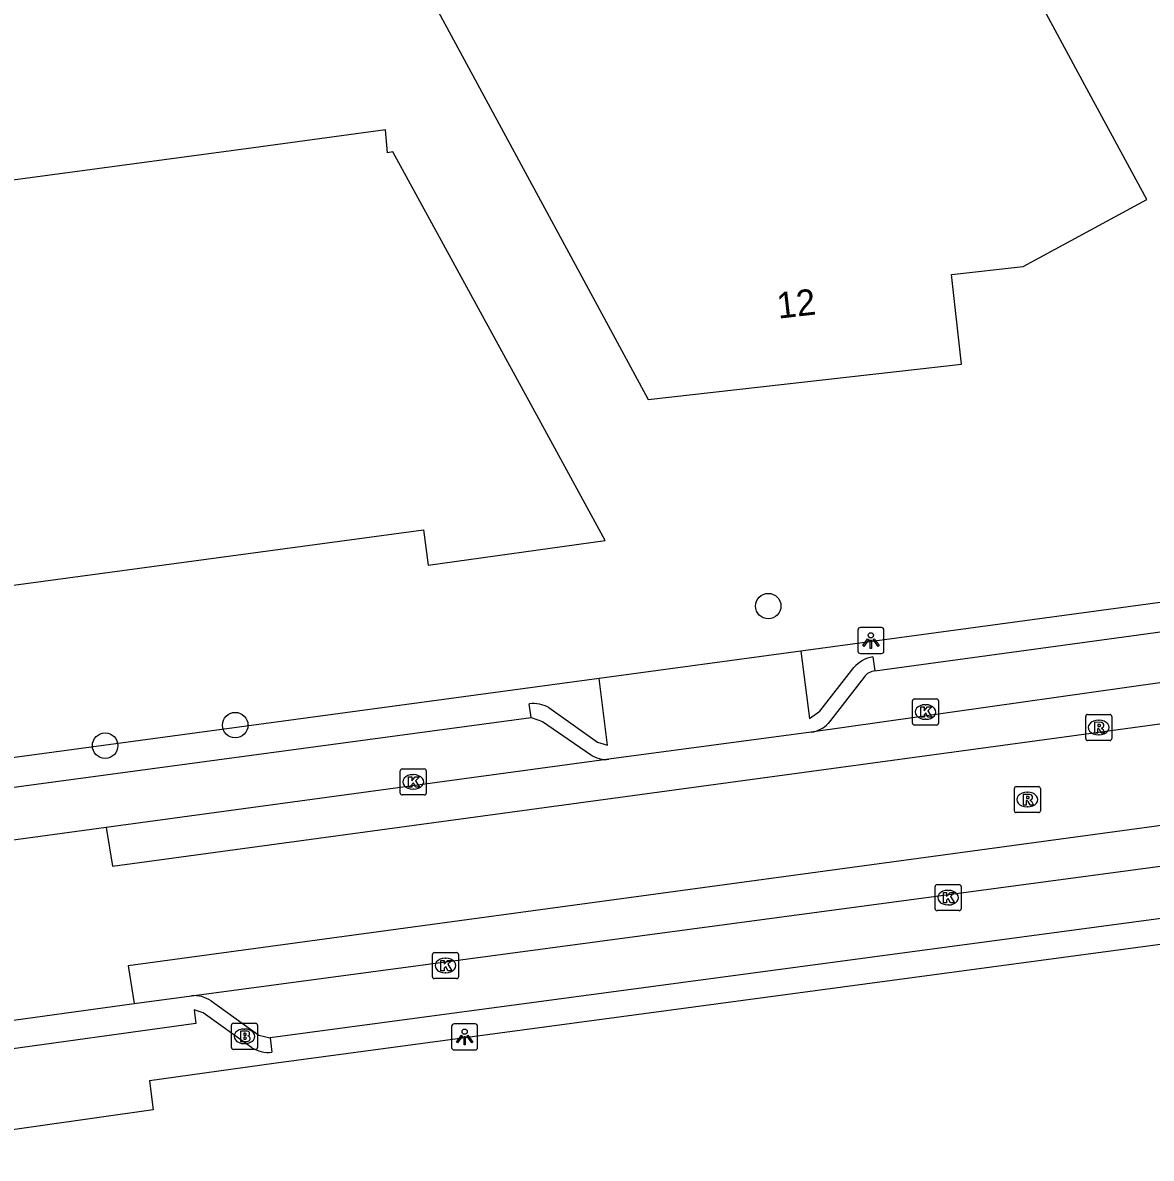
# Model space of a CAD drawing. Extents: x 158461 to 159795, y 387220 to 388672.
# Drawn here: x 158908.52 to 158951.86, y 387443.73 to 387487.32 of the extents above; entities that cross this region are included whole.
import ezdxf

# ---------------------------------------------------------------- set-up
doc = ezdxf.new("R2010")
doc.units = 0
for name, color, linetype in [('IMGEO_Boom', 7, 'Continuous'), ('IMGEO_Brandkraan', 7, 'Continuous'), ('IMGEO_Kolk', 7, 'Continuous'), ('IMGEO_Lichtpunt', 7, 'Continuous'), ('IMGEO_Pand', 7, 'Continuous'), ('IMGEO_Pand_nummerreeks', 7, 'Continuous'), ('IMGEO_Rijbaan_lokaal_gesloten', 7, 'Continuous'), ('IMGEO_Rioolput', 7, 'Continuous'), ('IMGEO_Voetpad_open', 7, 'Continuous')]:
    doc.layers.add(name, color=color, linetype=linetype)

msp = doc.modelspace()

# ---------------------------------------------------------------- linework, layer by layer
at = {"layer": 'IMGEO_Boom'}
for centre in [(158937.148, 387464.927), (158916.678, 387460.357), (158911.683, 387459.569)]:
    msp.add_circle(centre, 0.489, dxfattribs=at)
at = {"layer": 'IMGEO_Brandkraan'}
for p, q in [((158916.534, 387447.985), (158916.534, 387448.837)), ((158916.609, 387448.911), (158917.461, 387448.911)), ((158917.022, 387448.691), (158917.047, 387448.691)), ((158917.535, 387448.837), (158917.535, 387447.985)), ((158917.461, 387447.911), (158916.609, 387447.911)), ((158917.045, 387448.131), (158917.02, 387448.131))]:
    msp.add_line(p, q, dxfattribs=at)
for points in [[(158916.534, 387447.985), (158916.534, 387448.837)], [(158916.609, 387448.911), (158917.461, 387448.911)], [(158917.535, 387448.837), (158917.535, 387447.985)], [(158916.882, 387448.611), (158916.882, 387448.211), (158917.095, 387448.211)], [(158917.113, 387448.611), (158916.882, 387448.611)], [(158917.061, 387448.53), (158917.007, 387448.53), (158917.007, 387448.454)], [(158917.007, 387448.454), (158917.06, 387448.454)], [(158917.069, 387448.378), (158917.007, 387448.378), (158917.007, 387448.297)], [(158917.007, 387448.297), (158917.069, 387448.297)], [(158917.461, 387447.911), (158916.609, 387447.911)]]:
    msp.add_lwpolyline(points, dxfattribs=at)
for centre, radius, start, end in [((158916.611, 387448.835), 0.0765, 91.552, 178.448), ((158916.611, 387448.835), 0.0765, 91.552, 178.448), ((158917.459, 387448.835), 0.0765, 1.552, 88.448), ((158917.459, 387448.835), 0.0765, 1.552, 88.448), ((158917.062, 387448.492), 0.0379, 267.8285, 90.9355), ((158917.07, 387448.337), 0.0404, 269.8759, 90.5077), ((158917.101, 387448.462), 0.251, 268.6676, 293.5347), ((158917.117, 387448.466), 0.145, 59.4692, 91.5367), ((158917.142, 387448.513), 0.0922, 285.5137, 58.1501), ((158917.147, 387448.321), 0.105, 301.3115, 78.989), ((158916.611, 387447.987), 0.0765, 181.552, 268.448), ((158916.611, 387447.987), 0.0765, 181.552, 268.448), ((158917.459, 387447.987), 0.0765, 271.552, 358.448), ((158917.459, 387447.987), 0.0765, 271.552, 358.448)]:
    msp.add_arc(centre, radius, start, end, dxfattribs=at)
for centre, major_axis, ratio, start_param, end_param in [((158917.021, 387448.411), (-0.387, 0.002), 0.722429, 4.712389, 7.853982), ((158917.046, 387448.411), (-0.39, 0.002), 0.717154, 1.570796, 4.712389)]:
    msp.add_ellipse(centre, major_axis=major_axis, ratio=ratio, start_param=start_param, end_param=end_param, dxfattribs=at)
at = {"layer": 'IMGEO_Kolk'}
for p, q in [((158942.687, 387460.435), (158942.687, 387461.287)), ((158942.762, 387461.361), (158943.614, 387461.361)), ((158943.688, 387461.287), (158943.688, 387460.435)), ((158943.175, 387461.141), (158943.2, 387461.141)), ((158943.198, 387460.581), (158943.173, 387460.581)), ((158943.614, 387460.361), (158942.762, 387460.361)), ((158923.089, 387458.676), (158923.941, 387458.676)), ((158923.014, 387457.75), (158923.014, 387458.602)), ((158923.502, 387458.456), (158923.527, 387458.456)), ((158924.015, 387458.602), (158924.015, 387457.75)), ((158923.525, 387457.896), (158923.5, 387457.896)), ((158923.941, 387457.676), (158923.089, 387457.676)), ((158943.556, 387453.309), (158943.556, 387454.161)), ((158943.631, 387454.235), (158944.483, 387454.235)), ((158944.044, 387454.015), (158944.069, 387454.015)), ((158944.557, 387454.161), (158944.557, 387453.309)), ((158944.067, 387453.455), (158944.042, 387453.455)), ((158944.483, 387453.235), (158943.631, 387453.235)), ((158924.253, 387450.701), (158924.253, 387451.553)), ((158924.328, 387451.627), (158925.18, 387451.627)), ((158924.741, 387451.407), (158924.766, 387451.407)), ((158925.254, 387451.553), (158925.254, 387450.701)), ((158924.764, 387450.847), (158924.739, 387450.847)), ((158925.18, 387450.627), (158924.328, 387450.627))]:
    msp.add_line(p, q, dxfattribs=at)
for points in [[(158942.687, 387460.435), (158942.687, 387461.287)], [(158942.762, 387461.361), (158943.614, 387461.361)], [(158943.688, 387461.287), (158943.688, 387460.435)], [(158943.008, 387461.061), (158943.131, 387461.061), (158943.131, 387460.91), (158943.261, 387461.061), (158943.425, 387461.061), (158943.279, 387460.91), (158943.432, 387460.661), (158943.28, 387460.661), (158943.195, 387460.825), (158943.131, 387460.758), (158943.131, 387460.661), (158943.008, 387460.661), (158943.008, 387461.061)], [(158943.614, 387460.361), (158942.762, 387460.361)], [(158923.089, 387458.676), (158923.941, 387458.676)], [(158923.014, 387457.75), (158923.014, 387458.602)], [(158923.335, 387458.376), (158923.458, 387458.376), (158923.458, 387458.225), (158923.588, 387458.376), (158923.752, 387458.376), (158923.606, 387458.225), (158923.759, 387457.976), (158923.607, 387457.976), (158923.522, 387458.14), (158923.458, 387458.073), (158923.458, 387457.976), (158923.335, 387457.976), (158923.335, 387458.376)], [(158924.015, 387458.602), (158924.015, 387457.75)], [(158923.941, 387457.676), (158923.089, 387457.676)], [(158943.556, 387453.309), (158943.556, 387454.161)], [(158943.631, 387454.235), (158944.483, 387454.235)], [(158943.877, 387453.935), (158944, 387453.935), (158944, 387453.784), (158944.13, 387453.935), (158944.294, 387453.935), (158944.148, 387453.784), (158944.301, 387453.535), (158944.149, 387453.535), (158944.064, 387453.699), (158944, 387453.632), (158944, 387453.535), (158943.877, 387453.535), (158943.877, 387453.935)], [(158944.557, 387454.161), (158944.557, 387453.309)], [(158944.483, 387453.235), (158943.631, 387453.235)], [(158924.253, 387450.701), (158924.253, 387451.553)], [(158924.328, 387451.627), (158925.18, 387451.627)], [(158924.574, 387451.327), (158924.697, 387451.327), (158924.697, 387451.176), (158924.827, 387451.327), (158924.991, 387451.327), (158924.845, 387451.176), (158924.998, 387450.927), (158924.846, 387450.927), (158924.761, 387451.091), (158924.697, 387451.024), (158924.697, 387450.927), (158924.574, 387450.927), (158924.574, 387451.327)], [(158925.254, 387451.553), (158925.254, 387450.701)], [(158925.18, 387450.627), (158924.328, 387450.627)]]:
    msp.add_lwpolyline(points, dxfattribs=at)
for centre, start, end in [((158942.764, 387461.285), 91.552, 178.448), ((158942.764, 387461.285), 91.552, 178.448), ((158943.612, 387461.285), 1.552, 88.448), ((158943.612, 387461.285), 1.552, 88.448), ((158942.764, 387460.437), 181.552, 268.448), ((158942.764, 387460.437), 181.552, 268.448), ((158943.612, 387460.437), 271.552, 358.448), ((158943.612, 387460.437), 271.552, 358.448), ((158923.091, 387458.6), 91.552, 178.448), ((158923.091, 387458.6), 91.552, 178.448), ((158923.939, 387458.6), 1.552, 88.448), ((158923.939, 387458.6), 1.552, 88.448), ((158923.091, 387457.752), 181.552, 268.448), ((158923.091, 387457.752), 181.552, 268.448), ((158923.939, 387457.752), 271.552, 358.448), ((158923.939, 387457.752), 271.552, 358.448), ((158943.633, 387454.159), 91.552, 178.448), ((158943.633, 387454.159), 91.552, 178.448), ((158944.481, 387454.159), 1.552, 88.448), ((158944.481, 387454.159), 1.552, 88.448), ((158943.633, 387453.311), 181.552, 268.448), ((158943.633, 387453.311), 181.552, 268.448), ((158944.481, 387453.311), 271.552, 358.448), ((158944.481, 387453.311), 271.552, 358.448), ((158924.33, 387451.551), 91.552, 178.448), ((158924.33, 387451.551), 91.552, 178.448), ((158925.178, 387451.551), 1.552, 88.448), ((158925.178, 387451.551), 1.552, 88.448), ((158924.33, 387450.703), 181.552, 268.448), ((158924.33, 387450.703), 181.552, 268.448), ((158925.178, 387450.703), 271.552, 358.448), ((158925.178, 387450.703), 271.552, 358.448)]:
    msp.add_arc(centre, 0.0765, start, end, dxfattribs=at)
for centre, major_axis, ratio, start_param, end_param in [((158943.174, 387460.861), (-0.387, 0.002), 0.722429, 4.712389, 7.853982), ((158943.199, 387460.861), (-0.39, 0.002), 0.717154, 1.570796, 4.712389), ((158923.501, 387458.176), (-0.387, 0.002), 0.722429, 4.712389, 7.853982), ((158923.526, 387458.176), (-0.39, 0.002), 0.717154, 1.570796, 4.712389), ((158944.043, 387453.735), (-0.387, 0.002), 0.722429, 4.712389, 7.853982), ((158944.068, 387453.735), (-0.39, 0.002), 0.717154, 1.570796, 4.712389), ((158924.74, 387451.127), (-0.387, 0.002), 0.722429, 4.712389, 7.853982), ((158924.765, 387451.127), (-0.39, 0.002), 0.717154, 1.570796, 4.712389)]:
    msp.add_ellipse(centre, major_axis=major_axis, ratio=ratio, start_param=start_param, end_param=end_param, dxfattribs=at)
at = {"layer": 'IMGEO_Lichtpunt'}
for p, q in [((158940.592, 387464.008), (158940.592, 387463.201)), ((158940.592, 387464.008), (158940.592, 387463.201)), ((158941.494, 387464.103), (158940.686, 387464.103)), ((158941.494, 387464.103), (158940.686, 387464.103)), ((158941.588, 387463.201), (158941.588, 387464.008)), ((158941.588, 387463.201), (158941.588, 387464.008)), ((158940.686, 387463.107), (158941.494, 387463.107)), ((158940.686, 387463.107), (158941.494, 387463.107)), ((158924.99, 387448.792), (158924.99, 387447.985)), ((158924.99, 387448.792), (158924.99, 387447.985)), ((158925.892, 387448.887), (158925.084, 387448.887)), ((158925.892, 387448.887), (158925.084, 387448.887)), ((158925.986, 387447.985), (158925.986, 387448.792)), ((158925.986, 387447.985), (158925.986, 387448.792)), ((158925.084, 387447.891), (158925.892, 387447.891)), ((158925.084, 387447.891), (158925.892, 387447.891))]:
    msp.add_line(p, q, dxfattribs=at)
for points in [[(158940.966, 387463.672), (158941.005, 387463.644), (158940.817, 387463.382), (158940.779, 387463.409), (158940.966, 387463.672)], [(158941.068, 387463.624), (158941.115, 387463.624), (158941.115, 387463.302), (158941.068, 387463.302), (158941.068, 387463.624)], [(158941.178, 387463.644), (158941.216, 387463.671), (158941.403, 387463.409), (158941.364, 387463.381), (158941.178, 387463.644)], [(158925.364, 387448.456), (158925.403, 387448.428), (158925.215, 387448.166), (158925.177, 387448.193), (158925.364, 387448.456)], [(158925.466, 387448.408), (158925.513, 387448.408), (158925.513, 387448.086), (158925.466, 387448.086), (158925.466, 387448.408)], [(158925.576, 387448.428), (158925.614, 387448.455), (158925.801, 387448.193), (158925.762, 387448.165), (158925.576, 387448.428)]]:
    msp.add_lwpolyline(points, dxfattribs=at)
for centre in [(158941.091, 387463.806), (158925.489, 387448.59)]:
    msp.add_circle(centre, 0.0994, dxfattribs=at)
for centre, start, end in [((158940.686, 387464.008), 90, 180), ((158940.686, 387464.008), 90, 180), ((158941.494, 387464.008), 0, 90), ((158941.494, 387464.008), 0, 90), ((158940.686, 387463.201), 180, 270), ((158940.686, 387463.201), 180, 270), ((158941.494, 387463.201), 270, 0), ((158941.494, 387463.201), 270, 360), ((158925.084, 387448.792), 90, 180), ((158925.084, 387448.792), 90, 180), ((158925.892, 387448.792), 0, 90), ((158925.892, 387448.792), 0, 90), ((158925.084, 387447.985), 180, 270), ((158925.084, 387447.985), 180, 270), ((158925.892, 387447.985), 270, 0), ((158925.892, 387447.985), 270, 360)]:
    msp.add_arc(centre, 0.0946, start, end, dxfattribs=at)
at = {"layer": 'IMGEO_Pand'}
for points in [[(158930.155, 387477.255), (158932.535, 387472.857), (158944.572, 387474.219), (158944.186, 387477.661), (158946.942, 387477.961), (158951.685, 387480.53), (158949.311, 387484.93), (158941.181, 387500), (158937.185, 387507.408), (158923.474, 387500), (158919.117, 387497.646), (158930.155, 387477.255)], [(158895.408, 387462.651), (158901.178, 387463.425), (158901.123, 387463.789), (158899.932, 387463.646), (158899.801, 387464.599), (158923.909, 387467.857), (158924.084, 387466.503), (158930.889, 387467.446), (158928.491, 387471.834), (158922.735, 387482.364), (158922.527, 387482.333), (158922.456, 387483.206), (158917.386, 387482.524), (158902.592, 387480.534), (158897.636, 387479.867), (158898, 387477.138), (158887.928, 387475.792)]]:
    msp.add_lwpolyline(points, dxfattribs=at)
at = {"layer": 'IMGEO_Rijbaan_lokaal_gesloten'}
for points in [[(158911.727, 387456.43), (158911.961, 387454.948), (158995.33, 387466.262), (159000.491, 387467.294), (159008.396, 387469.517), (159010.601, 387470.186), (159013.378, 387471.157), (159016.309, 387472.364), (159018.744, 387473.535), (159024.654, 387476.829), (159125.668, 387538.733), (159126.573, 387539.372), (159127.481, 387540.337), (159128.138, 387541.384), (159128.387, 387541.954), (159128.698, 387543.022), (159128.794, 387543.65), (159128.83, 387544.305), (159128.678, 387545.688), (159128.209, 387547.02)], [(159004.35, 387463.642), (158994.092, 387462.187), (158912.567, 387451.122), (158912.798, 387449.665)], [(158956.353, 387462.566), (158938.803, 387460.084)], [(158938.803, 387460.084), (158931.027, 387459.048)], [(158915, 387449.968), (158984.066, 387459.2)], [(158931.027, 387459.048), (158911.727, 387456.43)], [(158911.727, 387456.43), (158904.755, 387455.484)], [(158912.798, 387449.665), (158915, 387449.968)], [(158907.04, 387448.873), (158912.798, 387449.665)]]:
    msp.add_lwpolyline(points, dxfattribs=at)
at = {"layer": 'IMGEO_Rioolput'}
for p, q in [((158949.34, 387459.84), (158949.34, 387460.692)), ((158949.415, 387460.766), (158950.267, 387460.766)), ((158949.828, 387460.546), (158949.853, 387460.546)), ((158950.341, 387460.692), (158950.341, 387459.84)), ((158949.851, 387459.986), (158949.826, 387459.986)), ((158950.267, 387459.766), (158949.415, 387459.766)), ((158946.6, 387457.072), (158946.6, 387457.924)), ((158946.675, 387457.998), (158947.527, 387457.998)), ((158947.601, 387457.924), (158947.601, 387457.072)), ((158947.088, 387457.778), (158947.113, 387457.778)), ((158947.527, 387456.998), (158946.675, 387456.998)), ((158947.111, 387457.218), (158947.086, 387457.218))]:
    msp.add_line(p, q, dxfattribs=at)
for points in [[(158949.34, 387459.84), (158949.34, 387460.692)], [(158949.415, 387460.766), (158950.267, 387460.766)], [(158949.929, 387460.464), (158949.677, 387460.466), (158949.677, 387460.066)], [(158950.341, 387460.692), (158950.341, 387459.84)], [(158949.677, 387460.066), (158949.801, 387460.066), (158949.801, 387460.228), (158949.812, 387460.228)], [(158949.855, 387460.385), (158949.801, 387460.385), (158949.801, 387460.304)], [(158949.801, 387460.304), (158949.853, 387460.304)], [(158949.859, 387460.199), (158949.93, 387460.066), (158950.07, 387460.066), (158950.005, 387460.192)], [(158950.267, 387459.766), (158949.415, 387459.766)], [(158946.6, 387457.072), (158946.6, 387457.924)], [(158946.675, 387457.998), (158947.527, 387457.998)], [(158947.601, 387457.924), (158947.601, 387457.072)], [(158947.189, 387457.696), (158946.937, 387457.698), (158946.937, 387457.298)], [(158946.937, 387457.298), (158947.061, 387457.298), (158947.061, 387457.46), (158947.072, 387457.46)], [(158947.115, 387457.617), (158947.061, 387457.617), (158947.061, 387457.536)], [(158947.061, 387457.536), (158947.113, 387457.536)], [(158947.119, 387457.431), (158947.19, 387457.298), (158947.33, 387457.298), (158947.265, 387457.424)], [(158947.527, 387456.998), (158946.675, 387456.998)]]:
    msp.add_lwpolyline(points, dxfattribs=at)
for centre, radius, start, end in [((158949.417, 387460.69), 0.0765, 91.552, 178.448), ((158949.417, 387460.69), 0.0765, 91.552, 178.448), ((158949.928, 387460.354), 0.109, 350.3612, 89.416), ((158950.265, 387460.69), 0.0765, 1.552, 88.448), ((158950.265, 387460.69), 0.0765, 1.552, 88.448), ((158949.811, 387460.175), 0.0533, 26.0293, 88.6989), ((158949.837, 387460.493), 0.19, 274.7715, 282.9687), ((158949.861, 387460.289), 0.0964, 77.0061, 93.1865), ((158949.875, 387460.346), 0.0378, 276.6634, 79.6772), ((158949.926, 387460.354), 0.112, 277.5842, 350.9817), ((158949.91, 387460.139), 0.108, 29.5134, 73.7905), ((158949.417, 387459.842), 0.0765, 181.552, 268.448), ((158949.417, 387459.842), 0.0765, 181.552, 268.448), ((158950.265, 387459.842), 0.0765, 271.552, 358.448), ((158950.265, 387459.842), 0.0765, 271.552, 358.448), ((158946.677, 387457.922), 0.0765, 91.552, 178.448), ((158946.677, 387457.922), 0.0765, 91.552, 178.448), ((158947.525, 387457.922), 0.0765, 1.552, 88.448), ((158947.525, 387457.922), 0.0765, 1.552, 88.448), ((158947.071, 387457.407), 0.0533, 26.0293, 88.6989), ((158947.097, 387457.725), 0.19, 274.7715, 282.9687), ((158947.121, 387457.521), 0.0964, 77.0061, 93.1865), ((158947.135, 387457.578), 0.0378, 276.6634, 79.6772), ((158947.188, 387457.586), 0.109, 350.3612, 89.416), ((158947.186, 387457.586), 0.112, 277.5842, 350.9817), ((158947.17, 387457.371), 0.108, 29.5134, 73.7905), ((158946.677, 387457.074), 0.0765, 181.552, 268.448), ((158946.677, 387457.074), 0.0765, 181.552, 268.448), ((158947.525, 387457.074), 0.0765, 271.552, 358.448), ((158947.525, 387457.074), 0.0765, 271.552, 358.448)]:
    msp.add_arc(centre, radius, start, end, dxfattribs=at)
for centre, major_axis, ratio, start_param, end_param in [((158949.827, 387460.266), (-0.387, 0.002), 0.722429, 4.712389, 7.853982), ((158949.852, 387460.266), (-0.39, 0.002), 0.717154, 1.570796, 4.712389), ((158947.087, 387457.498), (-0.387, 0.002), 0.722429, 4.712389, 7.853982), ((158947.112, 387457.498), (-0.39, 0.002), 0.717154, 1.570796, 4.712389)]:
    msp.add_ellipse(centre, major_axis=major_axis, ratio=ratio, start_param=start_param, end_param=end_param, dxfattribs=at)
at = {"layer": 'IMGEO_Voetpad_open'}
for points in [[(158955.888, 387465.567), (158938.394, 387463.195)], [(158941.246, 387462.44), (158956.056, 387464.46)], [(158938.394, 387463.195), (158930.651, 387462.152)], [(158938.394, 387463.195), (158938.727, 387460.61), (158939.126, 387460.892), (158940.435, 387462.567)], [(158941.165, 387462.979), (158941.246, 387462.44)], [(158930.651, 387462.152), (158897.588, 387457.682)], [(158928.728, 387461.03), (158930.592, 387459.704), (158930.971, 387459.582), (158930.651, 387462.152)], [(158940.838, 387462.204), (158939.446, 387460.418)], [(158928.046, 387460.65), (158927.967, 387461.172)], [(158907.215, 387457.847), (158928.046, 387460.65)], [(158928.046, 387460.65), (158928.479, 387460.501), (158930.321, 387459.235)], [(159004.113, 387458.902), (158999.01, 387458.217), (158989.379, 387456.925), (158973.012, 387454.73), (158964.768, 387453.624), (158962.694, 387453.346), (158918.158, 387447.372), (158913.387, 387446.696), (158913.533, 387445.59), (158900.447, 387443.729)], [(158956.929, 387453.557), (158918.018, 387448.348)], [(158915.75, 387449.771), (158917.58, 387448.459), (158918.018, 387448.348)], [(158917.307, 387447.986), (158915.448, 387449.312), (158915.099, 387449.428), (158915.161, 387448.908), (158907.199, 387447.804), (158907.04, 387448.873)], [(158918.018, 387448.348), (158918.082, 387447.801)]]:
    msp.add_lwpolyline(points, dxfattribs=at)
for centre, radius, start, end in [((158941.381, 387461.743), 1.255, 99.9264, 138.9529), ((158941.289, 387461.894), 0.547, 94.5413, 145.5515), ((158928.128, 387459.926), 1.257, 61.4922, 97.3685), ((158938.62, 387461.223), 1.154, 279.1466, 315.7517), ((158930.909, 387460.03), 0.989, 233.5046, 276.8246), ((158915.097, 387448.812), 1.16, 55.7598, 94.8058), ((158917.948, 387448.955), 1.162, 236.5149, 276.6335)]:
    msp.add_arc(centre, radius, start, end, dxfattribs=at)

# ---------------------------------------------------------------- texts
at = {"layer": 'IMGEO_Pand_nummerreeks'}
msp.add_text('12', height=1, rotation=6.4556, dxfattribs=at).set_placement((158937.536, 387475.96))

doc.saveas('drawing.dxf')
